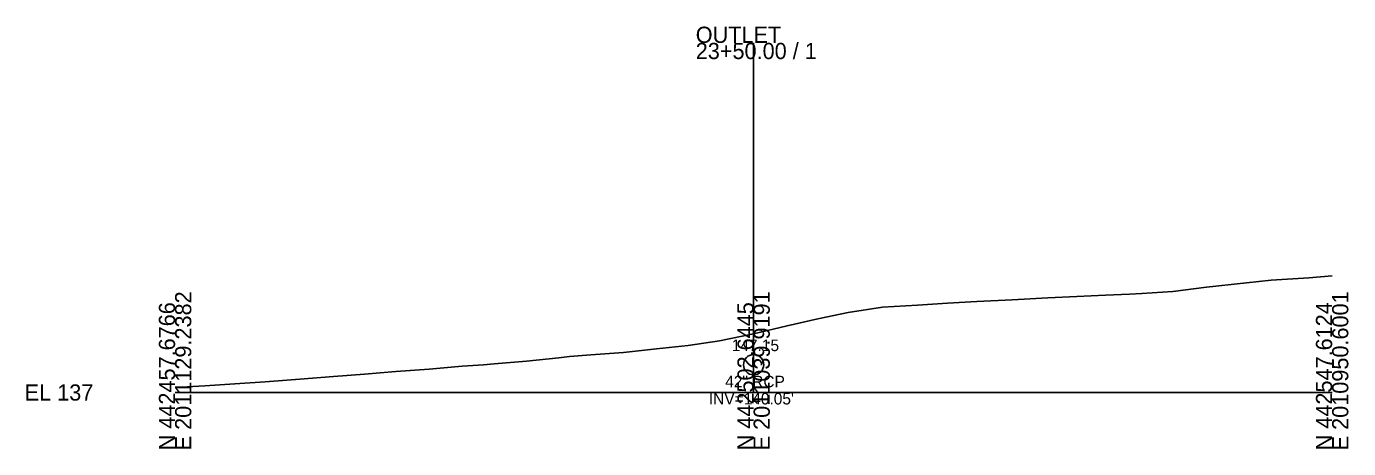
# Model space of a CAD drawing. Extents: x -26 to 1203, y -15 to 9526.
# Drawn here: x 974.3 to 1202.8, y 3490.3 to 3563.3 of the extents above; entities that cross this region are included whole.
import ezdxf

# ---------------------------------------------------------------- set-up
doc = ezdxf.new("R2010")
doc.units = 0
for name, color, linetype in [('Exist Cross Section Cell', 7, 'Continuous'), ('Exist XS Center Line Elevation Label', 7, 'Continuous'), ('Exist XS Ground Line', 7, 'Continuous'), ('Prop XSC Text', 7, 'Continuous')]:
    doc.layers.add(name, color=color, linetype=linetype)

msp = doc.modelspace()

# ---------------------------------------------------------------- linework, layer by layer
at = {"layer": 'Exist Cross Section Cell'}
for p, q in [((1100, 3500), (1100, 3560.44)), ((1000, 3500), (1100, 3500)), ((1100, 3500), (1200, 3500))]:
    msp.add_line(p, q, dxfattribs=at)
at = {"layer": 'Exist XS Ground Line'}
msp.add_lwpolyline([(1000, 3500.89), (1005.17, 3501.17), (1010.34, 3501.48), (1015.59, 3501.87), (1021.54, 3502.32), (1027.4, 3502.79), (1032.73, 3503.14), (1038.14, 3503.62), (1043.93, 3504.05), (1049.64, 3504.53), (1053.29, 3504.77), (1055.13, 3504.93), (1060.74, 3505.43), (1066.32, 3506.02), (1068.18, 3506.22), (1071.88, 3506.51), (1077.52, 3506.92), (1083.23, 3507.54), (1088.71, 3508.12), (1094.12, 3508.95), (1100, 3510.15), (1105.78, 3511.53), (1111.11, 3512.73), (1116.36, 3513.8), (1122.3, 3514.77), (1128.33, 3515.09), (1133.5, 3515.44), (1138.6, 3515.75), (1144.69, 3516.01), (1150.88, 3516.39), (1155.89, 3516.62), (1160.83, 3516.85), (1164.99, 3516.97), (1167.08, 3517.1), (1172.44, 3517.44), (1178.28, 3518.21), (1179.88, 3518.4), (1183.07, 3518.74), (1189.48, 3519.43), (1195.97, 3519.85), (1200, 3520.15)], dxfattribs=at)
at = {"layer": 'Prop XSC Text'}
msp.add_circle((1100, 3504.8), 1.75, dxfattribs=at)

# ---------------------------------------------------------------- texts
at = {"layer": 'Exist Cross Section Cell'}
for s, p in [('OUTLET', (1090, 3560.44)), ('23+50.00 / 1', (1090, 3557.64)), ('EL 137', (974, 3498.6))]:
    msp.add_text(s, height=2.8, dxfattribs=at).set_placement(p)
for s, p in [('E 2011129.2382', (1002.8, 3490)), ('E 2011039.9191', (1102.8, 3490)), ('E 2010950.6001', (1202.8, 3490)), ('N 442457.6766', (1000, 3490)), ('N 442502.6445', (1100, 3490)), ('N 442547.6124', (1200, 3490))]:
    msp.add_text(s, height=2.8, rotation=90, dxfattribs=at).set_placement(p)
at = {"layer": 'Exist XS Center Line Elevation Label'}
msp.add_text('147.15', height=2, dxfattribs=at).set_placement((1096.22, 3507.15))
at = {"layer": 'Prop XSC Text'}
for s, p in [('42" RCP', (1095.09, 3500.89)), ("INV=140.05'", (1092.26, 3497.93))]:
    msp.add_text(s, height=2, dxfattribs=at).set_placement(p)

doc.saveas('drawing.dxf')
